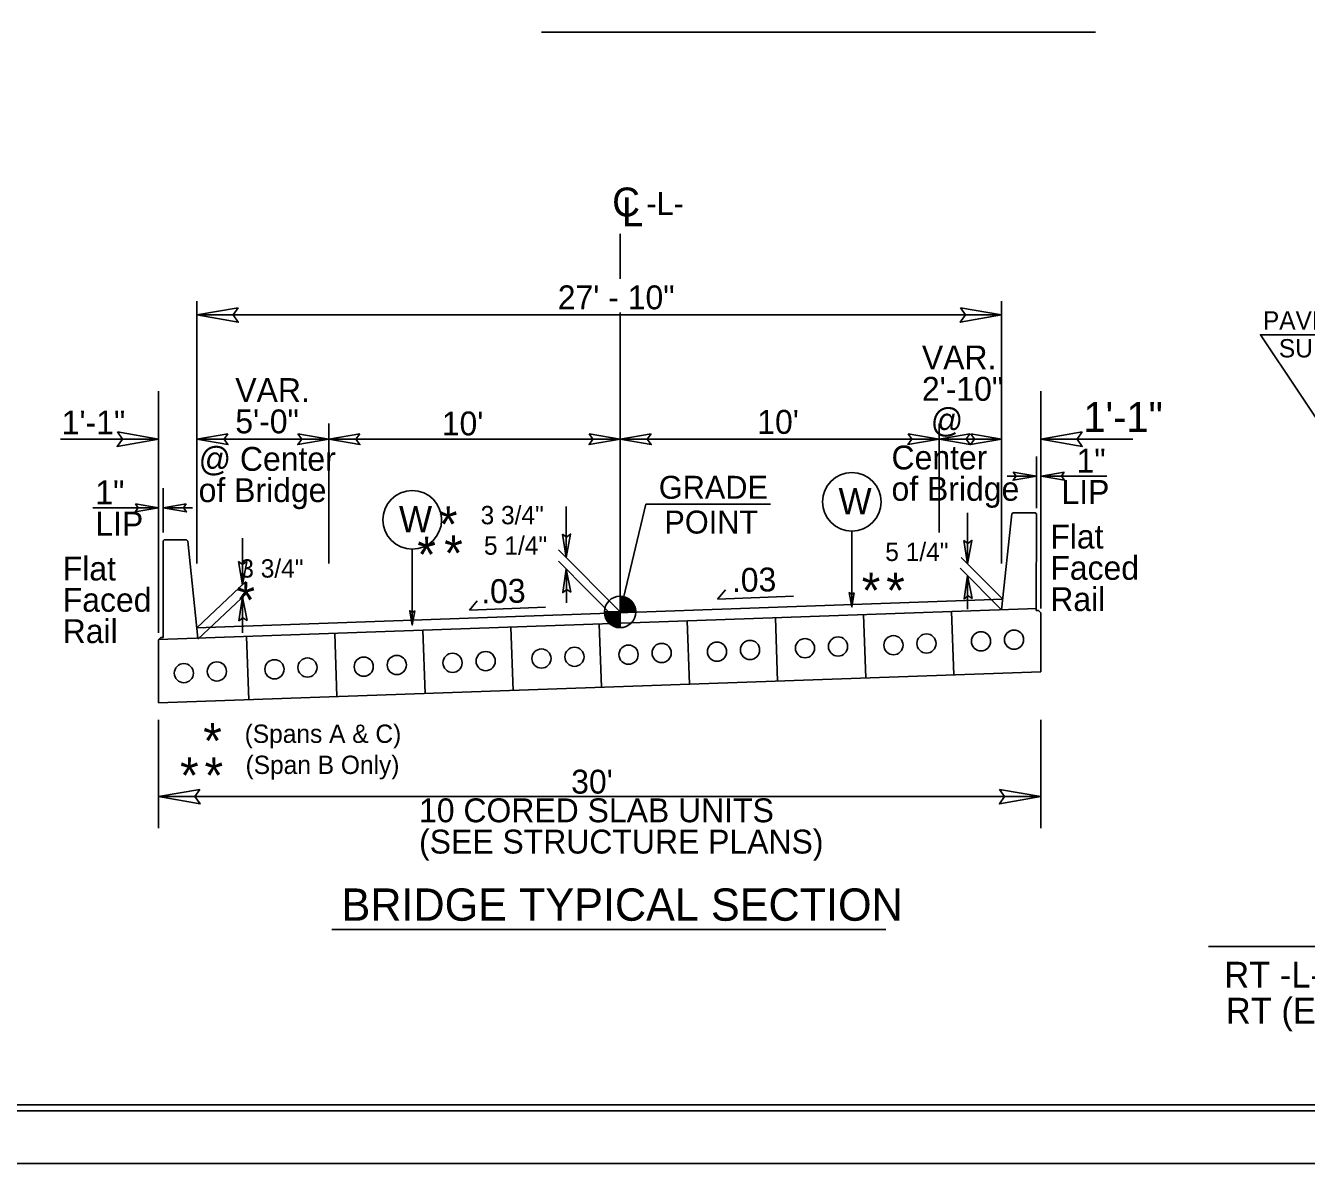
# Model space of a CAD drawing. Extents: x 573693 to 575619, y -55388 to -54288.
# Drawn here: x 574388 to 574934, y -55388 to -54903 of the extents above; entities that cross this region are included whole.
import ezdxf

# ---------------------------------------------------------------- set-up
doc = ezdxf.new("R2010")
doc.units = 0
for name, color, linetype in [('Default', 7, 'Continuous'), ('Old_Level_23', 7, 'Continuous'), ('Prop Dimension', 7, 'Continuous'), ('Prop Pavement Schedule Description CELL', 7, 'Continuous'), ('Sheet Border Standard 30in CELL', 7, 'Continuous'), ('Sheet Cutting Line CELL', 7, 'Continuous'), ('Sheet Plot Border Inside CELL', 7, 'Continuous'), ('Sheet Plot Border Outside CELL', 7, 'Continuous'), ('Typical Bridge Rail CELL', 7, 'Continuous'), ('Typical Grade Point Symbol CELL', 7, 'Continuous'), ('Typical ID Circle CELL', 7, 'Continuous'), ('Typical Terminator CELL', 7, 'Continuous'), ('Typical Text Centerline CELL', 7, 'Continuous'), ('Typical Text Grade Point CELL', 7, 'Continuous'), ('Typical Text ID Circle CELL', 7, 'Continuous')]:
    doc.layers.add(name, color=color, linetype=linetype)

msp = doc.modelspace()

# ---------------------------------------------------------------- linework, layer by layer
at = {"layer": 'Default'}
for p, q in [((574641.01, -54992.2), (574641.01, -55011.29)), ((574460.55, -55020.84), (574460.55, -55132.71)), ((574803.67, -55020.84), (574803.67, -55132.71)), ((574460.55, -55026.7), (574803.67, -55026.7)), ((574641.01, -55025.71), (574641.01, -55153.32)), ((574444.21, -55059.29), (574444.21, -55162.3)), ((574820.4, -55059.29), (574820.4, -55151.82)), ((574516.81, -55073.02), (574516.81, -55132.71)), ((574776.99, -55073.02), (574776.99, -55119.51)), ((574402.38, -55079.62), (574444.21, -55079.62)), ((574460.55, -55079.62), (574516.81, -55079.62)), ((574516.81, -55079.62), (574641.01, -55079.62)), ((574641.01, -55079.62), (574776.99, -55079.62)), ((574776.99, -55079.62), (574803.67, -55079.62)), ((574820.4, -55079.62), (574859.58, -55079.62)), ((574818.52, -55087.03), (574818.52, -55109.1)), ((574818.52, -55095.4), (574806.07, -55095.4)), ((574848.48, -55095.4), (574820.48, -55095.4)), ((574446.17, -55100.53), (574446.17, -55119.43)), ((574416.21, -55108.9), (574444.21, -55108.9)), ((574446.17, -55108.9), (574458.62, -55108.9)), ((574617.99, -55108.45), (574617.99, -55130.09)), ((574789.1, -55111.12), (574789.1, -55132.77)), ((574479.93, -55121.94), (574479.93, -55141.79)), ((574618.08, -55136.37), (574618.08, -55149.44)), ((574789.19, -55139.04), (574789.19, -55152.11)), ((574479.93, -55147.1), (574479.93, -55162.2)), ((574576.82, -55152.62), (574580.11, -55148.59)), ((574682.58, -55147.89), (574685.88, -55143.86)), ((574714.88, -55146.61), (574682.58, -55147.89)), ((574609.12, -55151.34), (574576.82, -55152.62)), ((574444.21, -55199.3), (574444.21, -55245.52)), ((574820.38, -55199.3), (574820.38, -55245.52)), ((574444.21, -55232.05), (574820.38, -55232.05))]:
    msp.add_line(p, q, dxfattribs=at)
at = {"layer": 'Old_Level_23'}
msp.add_lwpolyline([(574946.73, -55084.09), (574914.04, -55035.18), (574973.06, -55035.18)], dxfattribs=at)
at = {"layer": 'Prop Dimension'}
for p, q in [((574607.46, -54906.22), (574843.72, -54906.22)), ((574641.01, -55153.32), (574614.77, -55126.84)), ((574640.53, -55157.82), (574614.68, -55131.74)), ((574804.15, -55147.95), (574786.49, -55130.14)), ((574803.67, -55152.46), (574786.01, -55134.64)), ((574460.55, -55160.04), (574481.42, -55140.39)), ((574804.15, -55147.95), (574460.55, -55160.04)), ((574460.92, -55164.99), (574481.8, -55145.34)), ((574818.62, -55151.93), (574444.21, -55165.11)), ((574744.78, -55154.53), (574745.73, -55181.48)), ((574782.36, -55153.21), (574783.3, -55180.16)), ((574594.47, -55159.82), (574595.42, -55186.77)), ((574632.05, -55158.5), (574633, -55185.45)), ((574669.62, -55157.17), (574670.57, -55184.13)), ((574707.2, -55155.85), (574708.15, -55182.81)), ((574481.74, -55163.79), (574482.69, -55190.74)), ((574519.32, -55162.46), (574520.27, -55189.42)), ((574556.89, -55161.14), (574557.84, -55188.1)), ((574820.4, -55160.58), (574820.38, -55178.86)), ((574444.21, -55172.08), (574444.21, -55192.09)), ((574820.38, -55178.86), (574444.21, -55192.09)), ((574518.05, -55288.74), (574754.31, -55288.74)), ((574891.82, -55296), (575343.64, -55296))]:
    msp.add_line(p, q, dxfattribs=at)
for centre in [(574696.41, -55169.53), (574719.84, -55168.79), (574733.93, -55168.06), (574757.54, -55167.51), (574771.63, -55166.78), (574794.88, -55165.86), (574808.97, -55165.13), (574569.57, -55175.02), (574583.67, -55174.29), (574607.46, -55173.19), (574621.55, -55172.45), (574644.61, -55171.54), (574658.71, -55170.81), (574682.32, -55170.26), (574455, -55179.41), (574469.09, -55178.68), (574493.62, -55177.77), (574507.71, -55177.03), (574531.69, -55176.67), (574545.78, -55175.93)]:
    msp.add_circle(centre, 4.09, dxfattribs=at)
at = {"layer": 'Sheet Border Standard 30in CELL'}
msp.add_lwpolyline([(575359.97, -54313.39), (573859.97, -54313.39), (573859.97, -55363.39), (575359.97, -55363.39)], close=True, dxfattribs=at)
at = {"layer": 'Sheet Cutting Line CELL'}
msp.add_line((573692.97, -55388.39), (575376.97, -55388.39), dxfattribs=at)
at = {"layer": 'Sheet Plot Border Inside CELL'}
msp.add_lwpolyline([(575372.47, -54310.84), (573705.97, -54310.84), (573705.97, -55365.94), (575372.47, -55365.94)], close=True, dxfattribs=at)
at = {"layer": 'Sheet Plot Border Outside CELL'}
msp.add_lwpolyline([(575376.97, -54288.39), (573692.97, -54288.39), (573692.97, -55388.39), (575376.97, -55388.39)], close=True, dxfattribs=at)
at = {"layer": 'Typical Bridge Rail CELL'}
for p, q in [((574803.67, -55152.46), (574808.04, -55111.57)), ((574808.04, -55111.57), (574808.58, -55111.02)), ((574808.58, -55111.02), (574818.03, -55111.04)), ((574818.03, -55111.04), (574818.52, -55111.53)), ((574818.52, -55111.53), (574818.46, -55152.75)), ((574446.66, -55122.55), (574446.17, -55123.04)), ((574446.17, -55123.04), (574446.17, -55164.26)), ((574456.11, -55122.55), (574446.66, -55122.55)), ((574456.65, -55123.09), (574456.11, -55122.55)), ((574461.02, -55164.51), (574456.65, -55123.09)), ((574818.46, -55152.75), (574819.44, -55152.75)), ((574819.44, -55152.75), (574820.41, -55153.73)), ((574820.41, -55153.73), (574820.4, -55160.58)), ((574445.19, -55164.26), (574444.21, -55165.24)), ((574444.21, -55165.24), (574444.21, -55172.08)), ((574446.17, -55164.26), (574445.19, -55164.26))]:
    msp.add_line(p, q, dxfattribs=at)
at = {"layer": 'Typical Grade Point Symbol CELL'}
for p, q in [((574641.01, -55153.32), (574641.01, -55146.6)), ((574634.3, -55153.32), (574641.01, -55153.32)), ((574641, -55160.03), (574641.01, -55153.32)), ((574641.01, -55153.32), (574641, -55160.03)), ((574647.73, -55153.32), (574641.01, -55153.32))]:
    msp.add_line(p, q, dxfattribs=at)
for points in [[(574641.07, -55146.6), (574641.07, -55146.6), (574641.07, -55153.32)], [(574641.21, -55146.6), (574641.21, -55153.32)], [(574641.34, -55146.62), (574641.34, -55153.32)], [(574641.48, -55146.62), (574641.48, -55153.32)], [(574641.61, -55146.63), (574641.61, -55153.32)], [(574641.74, -55146.65), (574641.74, -55153.32)], [(574641.88, -55146.66), (574641.88, -55153.32)], [(574642.01, -55146.68), (574642.01, -55153.32)], [(574642.15, -55146.69), (574642.15, -55153.32)], [(574642.28, -55146.72), (574642.28, -55153.32)], [(574642.42, -55146.75), (574642.42, -55153.32)], [(574642.55, -55146.78), (574642.55, -55153.32)], [(574642.68, -55146.81), (574642.68, -55153.32)], [(574642.82, -55146.86), (574642.82, -55153.32)], [(574642.95, -55146.89), (574642.95, -55153.32)], [(574643.09, -55146.93), (574643.09, -55153.32)], [(574643.22, -55146.98), (574643.22, -55153.32)], [(574643.36, -55147.02), (574643.36, -55153.32)], [(574643.49, -55147.08), (574643.49, -55153.32)], [(574643.62, -55147.14), (574643.62, -55153.32)], [(574643.76, -55147.2), (574643.76, -55153.32)], [(574643.89, -55147.26), (574643.89, -55153.32)], [(574644.03, -55147.32), (574644.03, -55153.32)], [(574644.16, -55147.39), (574644.16, -55153.32)], [(574644.3, -55147.47), (574644.3, -55153.32)], [(574644.43, -55147.54), (574644.43, -55153.32)], [(574644.56, -55147.62), (574644.56, -55153.32)], [(574644.7, -55147.71), (574644.7, -55153.32)], [(574644.83, -55147.8), (574644.83, -55153.32)], [(574644.97, -55147.9), (574644.97, -55153.32)], [(574645.1, -55147.99), (574645.1, -55153.32)], [(574645.24, -55148.1), (574645.24, -55153.32)], [(574645.37, -55148.21), (574645.37, -55153.32)], [(574645.5, -55148.33), (574645.5, -55153.32)], [(574645.64, -55148.45), (574645.64, -55153.32)], [(574645.77, -55148.59), (574645.77, -55153.32)], [(574645.91, -55148.72), (574645.91, -55153.32)], [(574646.04, -55148.87), (574646.04, -55153.32)], [(574646.18, -55149.03), (574646.18, -55153.32)], [(574646.31, -55149.2), (574646.31, -55153.32)], [(574634.33, -55153.32), (574634.33, -55154.05)], [(574634.46, -55153.32), (574634.46, -55154.84)], [(574634.6, -55153.32), (574634.6, -55155.32)], [(574634.73, -55153.32), (574634.73, -55155.72)], [(574634.87, -55153.32), (574634.87, -55156.03)], [(574635, -55153.32), (574635, -55156.32)], [(574635.14, -55153.32), (574635.14, -55156.57)], [(574635.27, -55153.32), (574635.27, -55156.81)], [(574635.4, -55153.32), (574635.4, -55157.02)], [(574635.54, -55153.32), (574635.54, -55157.21)], [(574635.67, -55153.32), (574635.67, -55157.39)], [(574635.81, -55153.32), (574635.81, -55157.55)], [(574635.94, -55153.32), (574635.94, -55157.72)], [(574636.07, -55153.32), (574636.07, -55157.87)], [(574636.21, -55153.32), (574636.21, -55158.02)], [(574636.34, -55153.32), (574636.34, -55158.15)], [(574636.48, -55153.32), (574636.48, -55158.27)], [(574636.61, -55153.32), (574636.61, -55158.39)], [(574636.75, -55153.32), (574636.75, -55158.51)], [(574636.88, -55153.32), (574636.88, -55158.61)], [(574637.02, -55153.32), (574637.02, -55158.72)], [(574637.15, -55153.32), (574637.15, -55158.81)], [(574637.28, -55153.32), (574637.28, -55158.9)], [(574637.42, -55153.32), (574637.42, -55158.99)], [(574637.55, -55153.32), (574637.55, -55159.08)], [(574637.69, -55153.32), (574637.69, -55159.15)], [(574637.82, -55153.32), (574637.82, -55159.22)], [(574637.95, -55153.32), (574637.95, -55159.3)], [(574638.09, -55153.32), (574638.09, -55159.36)], [(574638.22, -55153.32), (574638.22, -55159.42)], [(574638.36, -55153.32), (574638.36, -55159.48)], [(574638.49, -55153.32), (574638.49, -55159.54)], [(574638.63, -55153.32), (574638.63, -55159.6)], [(574638.76, -55153.32), (574638.76, -55159.64)], [(574638.89, -55153.32), (574638.89, -55159.69)], [(574639.03, -55153.32), (574639.03, -55159.73)], [(574639.16, -55153.32), (574639.16, -55159.76)], [(574639.3, -55153.32), (574639.3, -55159.81)], [(574639.43, -55153.32), (574639.43, -55159.84)], [(574639.57, -55153.32), (574639.57, -55159.87)], [(574639.7, -55153.32), (574639.7, -55159.9)], [(574639.83, -55153.32), (574639.83, -55159.93)], [(574639.97, -55153.32), (574639.97, -55159.94)], [(574640.1, -55153.32), (574640.1, -55159.97)], [(574640.24, -55153.32), (574640.24, -55159.99)], [(574640.37, -55153.32), (574640.37, -55160)], [(574640.51, -55153.32), (574640.51, -55160.02)], [(574640.64, -55153.32), (574640.64, -55160.02)], [(574640.77, -55153.32), (574640.77, -55160.03)], [(574640.91, -55153.32), (574640.91, -55160.03), (574640.91, -55160.03)], [(574646.44, -55149.38), (574646.44, -55153.32)], [(574646.58, -55149.57), (574646.58, -55153.32)], [(574646.71, -55149.78), (574646.71, -55153.32)], [(574646.85, -55150), (574646.85, -55153.32)], [(574646.98, -55150.24), (574646.98, -55153.32)], [(574647.12, -55150.53), (574647.12, -55153.32)], [(574647.25, -55150.84), (574647.25, -55153.32)], [(574647.38, -55151.21), (574647.38, -55153.32)], [(574647.52, -55151.68), (574647.52, -55153.32)], [(574647.65, -55152.36), (574647.65, -55153.32)]]:
    msp.add_lwpolyline(points, dxfattribs=at)
msp.add_circle((574641.01, -55153.32), 6.71, dxfattribs=at)
for start, end in [(359.9905, 89.9905), (179.9905, 269.9905)]:
    msp.add_arc((574641.01, -55153.32), 6.71, start, end, dxfattribs=at)
at = {"layer": 'Typical ID Circle CELL'}
for p, q in [((574739.81, -55118.91), (574739.81, -55151.22)), ((574552.4, -55126.6), (574552.4, -55158.91))]:
    msp.add_line(p, q, dxfattribs=at)
for centre in [(574739.81, -55106.41), (574552.4, -55114.1)]:
    msp.add_circle(centre, 12.5, dxfattribs=at)
at = {"layer": 'Typical Terminator CELL'}
for points in [[(574478.12, -55023.67), (574460.55, -55026.7), (574478.22, -55029.82), (574475.97, -55026.7)], [(574786.09, -55023.67), (574803.67, -55026.7), (574786, -55029.82), (574788.24, -55026.7)], [(574426.64, -55076.59), (574444.21, -55079.62), (574426.54, -55082.74), (574428.78, -55079.62)], [(574473.73, -55077.35), (574460.55, -55079.62), (574473.8, -55081.96), (574472.12, -55079.62)], [(574503.63, -55077.35), (574516.81, -55079.62), (574503.56, -55081.96), (574505.24, -55079.62)], [(574530, -55077.35), (574516.81, -55079.62), (574530.07, -55081.96), (574528.39, -55079.62)], [(574627.83, -55077.35), (574641.01, -55079.62), (574627.76, -55081.96), (574629.44, -55079.62)], [(574654.19, -55077.35), (574641.01, -55079.62), (574654.27, -55081.96), (574652.58, -55079.62)], [(574763.81, -55077.35), (574776.99, -55079.62), (574763.74, -55081.96), (574765.42, -55079.62)], [(574790.18, -55077.35), (574776.99, -55079.62), (574790.25, -55081.96), (574788.56, -55079.62)], [(574790.49, -55077.35), (574803.67, -55079.62), (574790.41, -55081.96), (574792.1, -55079.62)], [(574837.98, -55076.59), (574820.4, -55079.62), (574838.08, -55082.74), (574835.83, -55079.62)], [(574808.64, -55093.7), (574818.52, -55095.4), (574808.58, -55097.16), (574809.85, -55095.4)], [(574830.37, -55093.7), (574820.48, -55095.4), (574830.42, -55097.16), (574829.16, -55095.4)], [(574434.33, -55107.2), (574444.21, -55108.9), (574434.27, -55110.66), (574435.53, -55108.9)], [(574456.05, -55107.2), (574446.17, -55108.9), (574456.11, -55110.66), (574454.85, -55108.9)], [(574616.4, -55120.19), (574617.99, -55130.09), (574619.86, -55120.17), (574618.09, -55121.42)], [(574787.51, -55122.86), (574789.1, -55132.77), (574790.97, -55122.85), (574789.2, -55124.09)], [(574478.34, -55131.89), (574479.93, -55141.79), (574481.8, -55131.87), (574480.03, -55133.11)], [(574620.02, -55144.91), (574617.99, -55135.08), (574616.56, -55145.08), (574618.28, -55143.76)], [(574791.13, -55147.58), (574789.1, -55137.76), (574787.67, -55147.75), (574789.39, -55146.43)], [(574481.96, -55156.92), (574479.93, -55147.1), (574478.5, -55157.09), (574480.21, -55155.77)], [(574740.86, -55145.13), (574739.81, -55151.22), (574738.73, -55145.1), (574739.81, -55145.87)], [(574553.45, -55152.82), (574552.4, -55158.91), (574551.32, -55152.79), (574552.4, -55153.56)], [(574461.79, -55229.02), (574444.21, -55232.05), (574461.89, -55235.18), (574459.64, -55232.05)], [(574802.8, -55229.02), (574820.38, -55232.05), (574802.7, -55235.18), (574804.95, -55232.05)]]:
    msp.add_lwpolyline(points, close=True, dxfattribs=at)
at = {"layer": 'Typical Text Grade Point CELL'}
for q in [(574641.01, -55153.32), (574705.11, -55107.43)]:
    msp.add_line((574652.04, -55107.43), q, dxfattribs=at)

# ---------------------------------------------------------------- texts
at = {"layer": 'Old_Level_23'}
for s, p in [('PAVEMENT', (574915.07, -55032.96)), ('SURFACE', (574921.87, -55044.83))]:
    msp.add_text(s, height=7.81, dxfattribs=at).set_placement(p)
at = {"layer": 'Prop Pavement Schedule Description CELL'}
for s, height, p in [(' *', 15.259, (574558.08, -55123.57)), (' 3 3/4" ', 7.812, (574578.61, -55115.96)), (' *', 15.259, (574548.85, -55136.48)), (' *', 15.259, (574560.31, -55135.88)), (' 5 1/4" ', 7.812, (574580.04, -55128.94)), (' 5 1/4" ', 7.812, (574751.15, -55131.61)), (' 3 3/4" ', 7.812, (574476.16, -55138.69)), (' *', 15.259, (574738.34, -55151.78)), (' *', 15.259, (574748.77, -55151.78)), (' *', 15.259, (574471.74, -55155.88)), (' *', 15.259, (574457.58, -55215.9)), (' (Spans A & C)', 7.8125, (574478.02, -55209.15)), (' (Span B Only)', 7.8125, (574478.4, -55222.4)), (' *', 15.259, (574447.7, -55230.63)), (' *', 15.259, (574458.14, -55230.63))]:
    msp.add_text(s, height=height, dxfattribs=at).set_placement(p)
at = {"layer": 'Typical Text Centerline CELL'}
msp.add_text('C', height=12.3, dxfattribs=at).set_placement((574637.61, -54984.72))
msp.add_text('L', height=12.31, rotation=359.9469, dxfattribs=at).set_placement((574641.7, -54988.92))
at = {"layer": 'Typical Text Grade Point CELL'}
for s, height, p in [('-L-', 9.787, (574652.18, -54984.07)), ('27\' - 10"', 10.179, (574614.42, -55024.32)), ('VAR.', 10.179, (574769.68, -55049.96)), ('VAR.', 10.179, (574476.93, -55063.85)), ('2\'-10" ', 10.179, (574769.68, -55063.31)), ('5\'-0"', 10.179, (574476.93, -55077.2)), ("10'", 10.179, (574699.49, -55077.41)), (' @', 10.179, (574769.68, -55076.65)), ('1\'-1"', 12.723, (574838.52, -55076.59)), ('1\'-1"', 10.179, (574402.92, -55077.64)), ("10'", 10.179, (574564.96, -55078.08)), ('@ Center', 10.179, (574461.31, -55093.17)), ('Center', 10.179, (574756.72, -55092.59)), ('1"', 10.179, (574835.61, -55093.95)), ('1"', 10.179, (574417.25, -55107.45)), ('of Bridge', 10.179, (574461.31, -55106.51)), ('GRADE', 9.787, (574657.5, -55105.09)), ('of Bridge', 10.179, (574756.72, -55105.93)), ('LIP', 10.179, (574829.19, -55107.29)), ('LIP', 10.179, (574417.25, -55120.8)), ('POINT', 9.787, (574659.86, -55119.92)), ('Flat', 10.179, (574824.42, -55126.29)), ('Flat', 10.179, (574403.35, -55139.92)), ('Faced', 10.179, (574824.42, -55139.63)), ('Faced', 10.179, (574403.35, -55153.26)), ('Rail', 10.179, (574824.42, -55152.98)), ('Rail', 10.179, (574403.35, -55166.61)), ("30'", 10.179, (574620.14, -55230.77)), ('10 CORED SLAB UNITS', 10.1786, (574555.28, -55242.98)), ('(SEE STRUCTURE PLANS)', 10.1786, (574555.28, -55256.32)), ('BRIDGE TYPICAL SECTION', 13.7632, (574522.22, -55284.96)), ('RT -L- STA 14+12.75 TO (STA. 14+20.73 BEGIN APPR. SLAB)', 11.0105, (574898.58, -55313.47)), ('RT (END APPR. SLAB -L- STA. 15+85.27) TO STA. 15+93.25', 11.0105, (574899.25, -55328.82))]:
    msp.add_text(s, height=height, dxfattribs=at).set_placement(p)
for p in [(574688.75, -55144.86), (574581.87, -55149.66)]:
    msp.add_text('.03', height=10.179, rotation=0.9627, dxfattribs=at).set_placement(p)
at = {"layer": 'Typical Text ID Circle CELL'}
for p in [(574734.13, -55111.7), (574546.72, -55119.39)]:
    msp.add_text('W', height=11.19, dxfattribs=at).set_placement(p)

doc.saveas('drawing.dxf')
